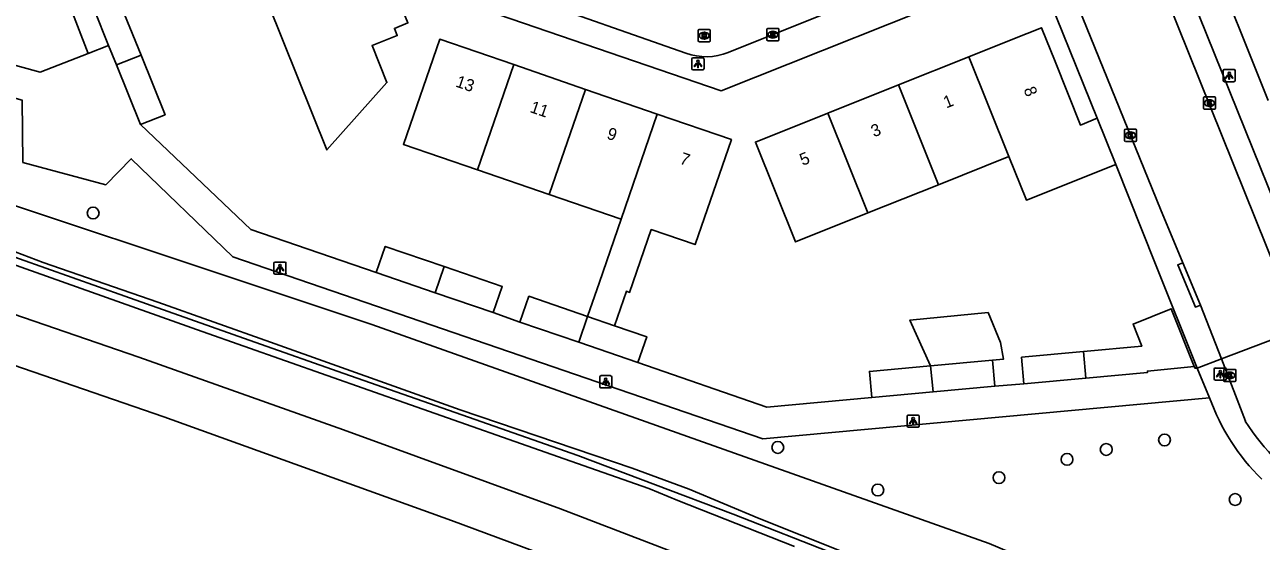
# Model space of a CAD drawing. Extents: x 162990 to 165007, y 383433 to 384336.
# Drawn here: x 163800.5 to 163902.7, y 383839.9 to 383882.7 of the extents above; entities that cross this region are included whole.
import ezdxf

# ---------------------------------------------------------------- set-up
doc = ezdxf.new("R2010")
doc.units = 0
for name, color, linetype in [('IMGEO_Boom', 7, 'Continuous'), ('IMGEO_Geluidsscherm', 7, 'Continuous'), ('IMGEO_Groenvoorziening', 7, 'Continuous'), ('IMGEO_Kolk', 7, 'Continuous'), ('IMGEO_Lichtpunt', 7, 'Continuous'), ('IMGEO_Muur', 7, 'Continuous'), ('IMGEO_Pand', 7, 'Continuous'), ('IMGEO_Pand_nummerreeks', 7, 'Continuous'), ('IMGEO_Rijbaan_lokaal_open', 7, 'Continuous'), ('IMGEO_Rioolput', 7, 'Continuous'), ('IMGEO_Spoor', 7, 'Continuous'), ('IMGEO_Spoorbaan_halfverhard', 7, 'Continuous'), ('IMGEO_Voetpad_open', 7, 'Continuous')]:
    doc.layers.add(name, color=color, linetype=linetype)

msp = doc.modelspace()

# ---------------------------------------------------------------- linework, layer by layer
at = {"layer": 'IMGEO_Boom'}
for centre in [(163806.18, 383867.07), (163894.75, 383848.3), (163862.78, 383847.68), (163889.93, 383847.51), (163886.69, 383846.69), (163881.06, 383845.18), (163871.05, 383844.15), (163900.59, 383843.37)]:
    msp.add_circle(centre, 0.489, dxfattribs=at)
at = {"layer": 'IMGEO_Geluidsscherm'}
msp.add_lwpolyline([(163774.05, 383875.4), (163781.73, 383872.71), (163782.12, 383872.57), (163783.25, 383869.74), (163787.97, 383868.23), (163797.39, 383864.74), (163802.04, 383862.98), (163811.54, 383859.69), (163820.83, 383856.4), (163836.52, 383850.79), (163850.74, 383845.96), (163855.44, 383844.22), (163861.23, 383841.81), (163878.61, 383834.88)], dxfattribs=at)
at = {"layer": 'IMGEO_Groenvoorziening'}
msp.add_lwpolyline([(163762.9, 383879.02), (163763.14, 383879.78), (163770.57, 383877.21), (163786.52, 383872.07), (163829.23, 383857.86), (163846.3, 383851.79), (163880.24, 383839.72), (163923.82, 383821.25), (163935.03, 383816.87), (163938.07, 383815.68), (164000, 383788.52), (164001.43, 383787.89), (164020.11, 383778.24), (164032.96, 383772.18), (164060.58, 383757.96), (164061.83, 383760.6)], dxfattribs=at)
at = {"layer": 'IMGEO_Kolk'}
for p, q in [((163861.87, 383881.41), (163861.87, 383882.26)), ((163861.95, 383882.33), (163862.8, 383882.33)), ((163862.87, 383882.26), (163862.87, 383881.41)), ((163862.8, 383881.33), (163861.95, 383881.33)), ((163862.36, 383882.11), (163862.39, 383882.11)), ((163862.38, 383881.55), (163862.36, 383881.55)), ((163897.97, 383875.75), (163897.97, 383876.6)), ((163898.04, 383876.68), (163898.89, 383876.68)), ((163898.45, 383876.45), (163898.48, 383876.45)), ((163898.97, 383876.6), (163898.97, 383875.75)), ((163898.89, 383875.67), (163898.04, 383875.67)), ((163898.48, 383875.9), (163898.45, 383875.9)), ((163891.43, 383873.08), (163891.43, 383873.93)), ((163891.51, 383874), (163892.36, 383874)), ((163891.92, 383873.78), (163891.95, 383873.78)), ((163891.94, 383873.22), (163891.92, 383873.22)), ((163892.44, 383873.93), (163892.44, 383873.08)), ((163892.36, 383873), (163891.51, 383873)), ((163899.65, 383853.21), (163899.65, 383854.06)), ((163899.72, 383854.14), (163900.57, 383854.14)), ((163900.13, 383853.92), (163900.16, 383853.92)), ((163900.65, 383854.06), (163900.65, 383853.21)), ((163900.57, 383853.14), (163899.72, 383853.14)), ((163900.16, 383853.36), (163900.13, 383853.36))]:
    msp.add_line(p, q, dxfattribs=at)
for points in [[(163861.87, 383881.41), (163861.87, 383882.26)], [(163861.95, 383882.33), (163862.8, 383882.33)], [(163862.87, 383882.26), (163862.87, 383881.41)], [(163862.8, 383881.33), (163861.95, 383881.33)], [(163862.19, 383882.03), (163862.32, 383882.03), (163862.32, 383881.88), (163862.45, 383882.03), (163862.61, 383882.03), (163862.46, 383881.88), (163862.62, 383881.63), (163862.46, 383881.63), (163862.38, 383881.8), (163862.32, 383881.73), (163862.32, 383881.63), (163862.19, 383881.63), (163862.19, 383882.03)], [(163897.97, 383875.75), (163897.97, 383876.6)], [(163898.04, 383876.68), (163898.89, 383876.68)], [(163898.29, 383876.37), (163898.41, 383876.37), (163898.41, 383876.22), (163898.54, 383876.37), (163898.7, 383876.37), (163898.56, 383876.22), (163898.71, 383875.97), (163898.56, 383875.97), (163898.47, 383876.14), (163898.41, 383876.07), (163898.41, 383875.97), (163898.29, 383875.97), (163898.29, 383876.37)], [(163898.97, 383876.6), (163898.97, 383875.75)], [(163898.89, 383875.67), (163898.04, 383875.67)], [(163891.43, 383873.08), (163891.43, 383873.93)], [(163891.51, 383874), (163892.36, 383874)], [(163891.75, 383873.7), (163891.88, 383873.7), (163891.88, 383873.55), (163892.01, 383873.7), (163892.17, 383873.7), (163892.03, 383873.55), (163892.18, 383873.3), (163892.03, 383873.3), (163891.94, 383873.47), (163891.88, 383873.4), (163891.88, 383873.3), (163891.75, 383873.3), (163891.75, 383873.7)], [(163892.44, 383873.93), (163892.44, 383873.08)], [(163892.36, 383873), (163891.51, 383873)], [(163899.65, 383853.21), (163899.65, 383854.06)], [(163899.72, 383854.14), (163900.57, 383854.14)], [(163899.97, 383853.84), (163900.09, 383853.84), (163900.09, 383853.69), (163900.22, 383853.84), (163900.38, 383853.84), (163900.24, 383853.69), (163900.39, 383853.44), (163900.24, 383853.44), (163900.15, 383853.6), (163900.09, 383853.54), (163900.09, 383853.44), (163899.97, 383853.44), (163899.97, 383853.84)], [(163900.65, 383854.06), (163900.65, 383853.21)], [(163900.57, 383853.14), (163899.72, 383853.14)]]:
    msp.add_lwpolyline(points, dxfattribs=at)
for centre, start, end in [((163861.95, 383882.26), 91.552, 178.448), ((163861.95, 383882.26), 91.552, 178.448), ((163862.8, 383882.26), 1.552, 88.448), ((163862.8, 383882.26), 1.552, 88.448), ((163861.95, 383881.41), 181.552, 268.448), ((163861.95, 383881.41), 181.552, 268.448), ((163862.8, 383881.41), 271.552, 358.448), ((163862.8, 383881.41), 271.552, 358.448), ((163898.04, 383876.6), 91.552, 178.448), ((163898.04, 383876.6), 91.552, 178.448), ((163898.89, 383876.6), 1.552, 88.448), ((163898.89, 383876.6), 1.552, 88.448), ((163898.04, 383875.75), 181.552, 268.448), ((163898.04, 383875.75), 181.552, 268.448), ((163898.89, 383875.75), 271.552, 358.448), ((163898.89, 383875.75), 271.552, 358.448), ((163891.51, 383873.93), 91.552, 178.448), ((163891.51, 383873.93), 91.552, 178.448), ((163891.51, 383873.08), 181.552, 268.448), ((163891.51, 383873.08), 181.552, 268.448), ((163892.36, 383873.93), 1.552, 88.448), ((163892.36, 383873.93), 1.552, 88.448), ((163892.36, 383873.08), 271.552, 358.448), ((163892.36, 383873.08), 271.552, 358.448), ((163899.72, 383854.06), 91.552, 178.448), ((163899.72, 383854.06), 91.552, 178.448), ((163900.57, 383854.06), 1.552, 88.448), ((163900.57, 383854.06), 1.552, 88.448), ((163899.72, 383853.21), 181.552, 268.448), ((163899.72, 383853.21), 181.552, 268.448), ((163900.57, 383853.21), 271.552, 358.448), ((163900.57, 383853.21), 271.552, 358.448)]:
    msp.add_arc(centre, 0.0765, start, end, dxfattribs=at)
for centre, major_axis, ratio, start_param, end_param in [((163862.36, 383881.83), (-0.387, 0.002), 0.722429, 4.712389, 7.853982), ((163862.38, 383881.83), (-0.39, 0.002), 0.717154, 1.570796, 4.712389), ((163898.45, 383876.17), (-0.387, 0.002), 0.722429, 4.712389, 7.853982), ((163898.48, 383876.17), (-0.39, 0.002), 0.717154, 1.570796, 4.712389), ((163891.92, 383873.5), (-0.387, 0.002), 0.722429, 4.712389, 7.853982), ((163891.95, 383873.5), (-0.39, 0.002), 0.717154, 1.570796, 4.712389), ((163900.13, 383853.64), (-0.387, 0.002), 0.722429, 4.712389, 7.853982), ((163900.16, 383853.64), (-0.39, 0.002), 0.717154, 1.570796, 4.712389)]:
    msp.add_ellipse(centre, major_axis=major_axis, ratio=ratio, start_param=start_param, end_param=end_param, dxfattribs=at)
at = {"layer": 'IMGEO_Lichtpunt'}
for p, q in [((163855.68, 383879.82), (163855.68, 383879.01)), ((163855.68, 383879.82), (163855.68, 383879.01)), ((163856.58, 383879.91), (163855.78, 383879.91)), ((163856.58, 383879.91), (163855.78, 383879.91)), ((163856.68, 383879.01), (163856.68, 383879.82)), ((163856.68, 383879.01), (163856.68, 383879.82)), ((163855.78, 383878.92), (163856.58, 383878.92)), ((163855.78, 383878.92), (163856.58, 383878.92)), ((163899.6, 383878.84), (163899.6, 383878.04)), ((163899.6, 383878.84), (163899.6, 383878.04)), ((163900.5, 383878.94), (163899.69, 383878.94)), ((163900.5, 383878.94), (163899.69, 383878.94)), ((163900.6, 383878.04), (163900.6, 383878.84)), ((163900.6, 383878.04), (163900.6, 383878.84)), ((163899.69, 383877.94), (163900.5, 383877.94)), ((163899.69, 383877.94), (163900.5, 383877.94)), ((163821.13, 383862.92), (163821.13, 383862.12)), ((163821.13, 383862.92), (163821.13, 383862.12)), ((163822.03, 383863.02), (163821.22, 383863.02)), ((163822.03, 383863.02), (163821.22, 383863.02)), ((163822.12, 383862.12), (163822.12, 383862.92)), ((163822.12, 383862.12), (163822.12, 383862.92)), ((163821.22, 383862.02), (163822.03, 383862.02)), ((163821.22, 383862.02), (163822.03, 383862.02)), ((163848.96, 383853.62), (163848.16, 383853.62)), ((163848.96, 383853.62), (163848.16, 383853.62)), ((163898.86, 383854.16), (163898.86, 383853.35)), ((163898.86, 383854.16), (163898.86, 383853.35)), ((163899.76, 383854.25), (163898.96, 383854.25)), ((163899.76, 383854.25), (163898.96, 383854.25)), ((163899.86, 383853.35), (163899.86, 383854.16)), ((163899.86, 383853.35), (163899.86, 383854.16)), ((163848.06, 383853.52), (163848.06, 383852.71)), ((163848.06, 383853.52), (163848.06, 383852.71)), ((163848.16, 383852.62), (163848.96, 383852.62)), ((163848.16, 383852.62), (163848.96, 383852.62)), ((163849.06, 383852.71), (163849.06, 383853.52)), ((163849.06, 383852.71), (163849.06, 383853.52)), ((163898.96, 383853.25), (163899.76, 383853.25)), ((163898.96, 383853.25), (163899.76, 383853.25)), ((163873.47, 383850.26), (163873.47, 383849.46)), ((163873.47, 383850.26), (163873.47, 383849.46)), ((163874.37, 383850.36), (163873.57, 383850.36)), ((163874.37, 383850.36), (163873.57, 383850.36)), ((163874.47, 383849.46), (163874.47, 383850.26)), ((163874.47, 383849.46), (163874.47, 383850.26)), ((163873.57, 383849.36), (163874.37, 383849.36)), ((163873.57, 383849.36), (163874.37, 383849.36))]:
    msp.add_line(p, q, dxfattribs=at)
for points in [[(163856.06, 383879.48), (163856.1, 383879.45), (163855.91, 383879.19), (163855.87, 383879.22), (163856.06, 383879.48)], [(163856.16, 383879.43), (163856.21, 383879.43), (163856.21, 383879.11), (163856.16, 383879.11), (163856.16, 383879.43)], [(163856.27, 383879.45), (163856.31, 383879.48), (163856.49, 383879.22), (163856.46, 383879.19), (163856.27, 383879.45)], [(163899.97, 383878.51), (163900.01, 383878.48), (163899.82, 383878.22), (163899.79, 383878.25), (163899.97, 383878.51)], [(163900.07, 383878.46), (163900.12, 383878.46), (163900.12, 383878.14), (163900.07, 383878.14), (163900.07, 383878.46)], [(163900.18, 383878.48), (163900.22, 383878.51), (163900.41, 383878.24), (163900.37, 383878.22), (163900.18, 383878.48)], [(163821.5, 383862.59), (163821.54, 383862.56), (163821.35, 383862.3), (163821.31, 383862.33), (163821.5, 383862.59)], [(163821.6, 383862.54), (163821.65, 383862.54), (163821.65, 383862.22), (163821.6, 383862.22), (163821.6, 383862.54)], [(163821.71, 383862.56), (163821.75, 383862.59), (163821.94, 383862.32), (163821.9, 383862.3), (163821.71, 383862.56)], [(163899.24, 383853.82), (163899.27, 383853.79), (163899.09, 383853.53), (163899.05, 383853.56), (163899.24, 383853.82)], [(163899.34, 383853.77), (163899.39, 383853.77), (163899.39, 383853.45), (163899.34, 383853.45), (163899.34, 383853.77)], [(163899.45, 383853.79), (163899.49, 383853.82), (163899.67, 383853.56), (163899.63, 383853.53), (163899.45, 383853.79)], [(163848.44, 383853.18), (163848.47, 383853.16), (163848.29, 383852.89), (163848.25, 383852.92), (163848.44, 383853.18)], [(163848.54, 383853.14), (163848.59, 383853.14), (163848.59, 383852.81), (163848.54, 383852.81), (163848.54, 383853.14)], [(163848.65, 383853.16), (163848.69, 383853.18), (163848.87, 383852.92), (163848.83, 383852.89), (163848.65, 383853.16)], [(163873.85, 383849.93), (163873.88, 383849.9), (163873.7, 383849.64), (163873.66, 383849.67), (163873.85, 383849.93)], [(163873.95, 383849.88), (163873.99, 383849.88), (163873.99, 383849.56), (163873.95, 383849.56), (163873.95, 383849.88)], [(163874.06, 383849.9), (163874.1, 383849.93), (163874.28, 383849.66), (163874.24, 383849.64), (163874.06, 383849.9)]]:
    msp.add_lwpolyline(points, dxfattribs=at)
for centre in [(163856.18, 383879.62), (163900.1, 383878.64), (163821.63, 383862.72), (163899.36, 383853.95), (163848.56, 383853.32), (163873.97, 383850.06)]:
    msp.add_circle(centre, 0.0994, dxfattribs=at)
for centre, start, end in [((163855.78, 383879.82), 90, 180), ((163855.78, 383879.82), 90, 180), ((163856.58, 383879.82), 0, 90), ((163856.58, 383879.82), 0, 90), ((163855.78, 383879.01), 180, 270), ((163855.78, 383879.01), 180, 270), ((163856.58, 383879.01), 270, 0), ((163856.58, 383879.01), 270, 360), ((163899.69, 383878.84), 90, 180), ((163899.69, 383878.84), 90, 180), ((163900.5, 383878.84), 0, 90), ((163900.5, 383878.84), 0, 90), ((163899.69, 383878.04), 180, 270), ((163899.69, 383878.04), 180, 270), ((163900.5, 383878.04), 270, 0), ((163900.5, 383878.04), 270, 360), ((163821.22, 383862.92), 90, 180), ((163821.22, 383862.92), 90, 180), ((163822.03, 383862.92), 0, 90), ((163822.03, 383862.92), 0, 90), ((163821.22, 383862.12), 180, 270), ((163821.22, 383862.12), 180, 270), ((163822.03, 383862.12), 270, 0), ((163822.03, 383862.12), 270, 360), ((163848.16, 383853.52), 90, 180), ((163848.16, 383853.52), 90, 180), ((163848.96, 383853.52), 0, 90), ((163848.96, 383853.52), 0, 90), ((163898.96, 383854.16), 90, 180), ((163898.96, 383854.16), 90, 180), ((163899.76, 383854.16), 0, 90), ((163899.76, 383854.16), 0, 90), ((163848.16, 383852.71), 180, 270), ((163848.16, 383852.71), 180, 270), ((163848.96, 383852.71), 270, 0), ((163848.96, 383852.71), 270, 360), ((163898.96, 383853.35), 180, 270), ((163898.96, 383853.35), 180, 270), ((163899.76, 383853.35), 270, 0), ((163899.76, 383853.35), 270, 360), ((163873.57, 383850.26), 90, 180), ((163873.57, 383850.26), 90, 180), ((163874.37, 383850.26), 0, 90), ((163874.37, 383850.26), 0, 90), ((163873.57, 383849.46), 180, 270), ((163873.57, 383849.46), 180, 270), ((163874.37, 383849.46), 270, 0), ((163874.37, 383849.46), 270, 360)]:
    msp.add_arc(centre, 0.0946, start, end, dxfattribs=at)
at = {"layer": 'IMGEO_Muur'}
for points in [[(163804.13, 383884.48), (163805.76, 383880.27)], [(163805.76, 383880.27), (163801.81, 383878.73), (163785.41, 383883.23), (163784.61, 383883.63)], [(163894.01, 383862.84), (163890.72, 383871.09)], [(163861.88, 383851), (163851.21, 383854.71)]]:
    msp.add_lwpolyline(points, dxfattribs=at)
at = {"layer": 'IMGEO_Pand'}
for points in [[(163820.64, 383884.38), (163825.51, 383872.3), (163830.47, 383877.86), (163829.24, 383880.92), (163831.32, 383881.76), (163831.08, 383882.35), (163832.2, 383882.8), (163831.18, 383885.31), (163830.07, 383884.86), (163828.92, 383887.71)], [(163806.26, 383883.92), (163808.29, 383884.74), (163810.14, 383880.14)], [(163806.26, 383883.92), (163807.46, 383880.94)], [(163878.58, 383880), (163882.2, 383881.45), (163884.58, 383882.4), (163885.7, 383879.6), (163887.8, 383874.35), (163889.19, 383874.91)], [(163837.95, 383870.65), (163831.83, 383872.75), (163834.83, 383881.45), (163840.95, 383879.35)], [(163808.11, 383879.33), (163807.46, 383880.94)], [(163810.14, 383880.14), (163808.11, 383879.33)], [(163808.11, 383879.33), (163810.1, 383874.39)], [(163810.1, 383874.39), (163812.13, 383875.21), (163810.14, 383880.14)], [(163840.95, 383879.35), (163837.95, 383870.65)], [(163846.89, 383877.3), (163840.95, 383879.35)], [(163872.75, 383877.67), (163878.58, 383880)], [(163881.89, 383871.74), (163878.58, 383880)], [(163843.89, 383868.6), (163846.89, 383877.3)], [(163846.89, 383877.3), (163852.82, 383875.26)], [(163866.92, 383875.34), (163872.75, 383877.67)], [(163872.75, 383877.67), (163876.06, 383869.41)], [(163849.28, 383857.75), (163850.26, 383860.6), (163850.53, 383860.5), (163852.32, 383865.7), (163855.94, 383864.46), (163858.94, 383873.15), (163852.82, 383875.26)], [(163852.82, 383875.26), (163849.83, 383866.56)], [(163870.23, 383867.08), (163864.24, 383864.68), (163860.93, 383872.94), (163866.92, 383875.34)], [(163870.23, 383867.08), (163866.92, 383875.34)], [(163889.19, 383874.91), (163890.72, 383871.09)], [(163881.89, 383871.74), (163876.06, 383869.41)], [(163890.72, 383871.09), (163883.33, 383868.14), (163881.89, 383871.74)], [(163837.95, 383870.65), (163843.89, 383868.6)], [(163876.06, 383869.41), (163870.23, 383867.08)], [(163849.83, 383866.56), (163843.89, 383868.6)], [(163849.83, 383866.56), (163848.04, 383861.36), (163847.06, 383858.52)], [(163835.2, 383862.64), (163830.33, 383864.31), (163829.59, 383862.15)], [(163829.59, 383862.15), (163834.46, 383860.48)], [(163834.46, 383860.48), (163835.2, 383862.64)], [(163839.26, 383858.84), (163840, 383860.99), (163835.2, 383862.64)], [(163834.46, 383860.48), (163839.26, 383858.84)], [(163847.06, 383858.52), (163842.2, 383860.19), (163841.46, 383858.05)], [(163880.53, 383854.9), (163881.45, 383854.99), (163881.18, 383856.37), (163880.16, 383858.84), (163873.7, 383858.22), (163875.4, 383854.43)], [(163888.05, 383855.61), (163892.86, 383856.05), (163892.15, 383857.89), (163895.3, 383859.15), (163897.21, 383854.37)], [(163841.46, 383858.05), (163846.33, 383856.38)], [(163846.33, 383856.38), (163847.06, 383858.52)], [(163847.06, 383858.52), (163849.28, 383857.75)], [(163851.21, 383854.71), (163851.94, 383856.84), (163849.28, 383857.75)], [(163846.33, 383856.38), (163851.21, 383854.71)], [(163880.53, 383854.9), (163875.4, 383854.43)], [(163880.73, 383852.75), (163880.53, 383854.9)], [(163883.13, 383852.95), (163882.93, 383855.14), (163888.05, 383855.61)], [(163888.05, 383855.61), (163888.25, 383853.42)], [(163875.4, 383854.43), (163870.35, 383853.97), (163870.55, 383851.82)], [(163875.61, 383852.28), (163875.4, 383854.43)], [(163888.25, 383853.42), (163893.35, 383853.89), (163893.34, 383853.99), (163897.21, 383854.37)], [(163875.61, 383852.28), (163880.73, 383852.75)], [(163883.13, 383852.95), (163888.25, 383853.42)], [(163870.55, 383851.82), (163875.61, 383852.28)]]:
    msp.add_lwpolyline(points, dxfattribs=at)
at = {"layer": 'IMGEO_Rijbaan_lokaal_open'}
for points in [[(163889.39, 383898.6), (163905.94, 383857.47)], [(163896.26, 383862.96), (163894.41, 383867.38), (163884.94, 383890.76)], [(163883.11, 383890.16), (163858.68, 383880.35)], [(163855.18, 383880.29), (163841.65, 383885.07), (163841.11, 383885.54)], [(163897.72, 383859.46), (163896.26, 383862.96)], [(163899.45, 383855), (163897.72, 383859.46)], [(163905.94, 383857.47), (163899.45, 383855)], [(163899.45, 383855), (163901.43, 383849.85)], [(163899.45, 383855), (163899.45, 383855)]]:
    msp.add_lwpolyline(points, dxfattribs=at)
for centre, radius, start, end in [((163856.85, 383884.93), 4.93, 250.224, 291.8682), ((163918.97, 383861.16), 20.87, 212.7923, 258.7749)]:
    msp.add_arc(centre, radius, start, end, dxfattribs=at)
at = {"layer": 'IMGEO_Rioolput'}
for p, q in [((163856.27, 383882.25), (163857.12, 383882.25)), ((163856.2, 383881.32), (163856.2, 383882.18)), ((163857.12, 383881.25), (163856.27, 383881.25)), ((163856.68, 383882.03), (163856.71, 383882.03)), ((163856.71, 383881.47), (163856.68, 383881.47)), ((163857.2, 383882.18), (163857.2, 383881.32))]:
    msp.add_line(p, q, dxfattribs=at)
for points in [[(163856.27, 383882.25), (163857.12, 383882.25)], [(163856.2, 383881.32), (163856.2, 383882.18)], [(163857.12, 383881.25), (163856.27, 383881.25)], [(163856.79, 383881.95), (163856.53, 383881.95), (163856.53, 383881.55)], [(163856.53, 383881.55), (163856.66, 383881.55), (163856.66, 383881.71), (163856.67, 383881.71)], [(163856.71, 383881.87), (163856.66, 383881.87), (163856.66, 383881.79)], [(163856.66, 383881.79), (163856.71, 383881.79)], [(163856.71, 383881.68), (163856.79, 383881.55), (163856.93, 383881.55), (163856.86, 383881.68)], [(163857.2, 383882.18), (163857.2, 383881.32)]]:
    msp.add_lwpolyline(points, dxfattribs=at)
for centre, radius, start, end in [((163856.27, 383882.18), 0.0765, 91.552, 178.448), ((163856.27, 383882.18), 0.0765, 91.552, 178.448), ((163857.12, 383882.18), 0.0765, 1.552, 88.448), ((163857.12, 383882.18), 0.0765, 1.552, 88.448), ((163856.27, 383881.33), 0.0765, 181.552, 268.448), ((163856.27, 383881.33), 0.0765, 181.552, 268.448), ((163856.67, 383881.66), 0.0533, 26.0293, 88.6989), ((163856.72, 383881.77), 0.0964, 77.0061, 93.1865), ((163856.69, 383881.98), 0.19, 274.7715, 282.9687), ((163856.73, 383881.83), 0.0378, 276.6634, 79.6772), ((163856.78, 383881.84), 0.109, 350.3612, 89.416), ((163856.78, 383881.84), 0.112, 277.5842, 350.9817), ((163856.77, 383881.62), 0.108, 29.5134, 73.7905), ((163857.12, 383881.33), 0.0765, 271.552, 358.448), ((163857.12, 383881.33), 0.0765, 271.552, 358.448)]:
    msp.add_arc(centre, radius, start, end, dxfattribs=at)
for centre, major_axis, ratio, start_param, end_param in [((163856.68, 383881.75), (-0.387, 0.002), 0.722429, 4.712389, 7.853982), ((163856.71, 383881.75), (-0.39, 0.002), 0.717154, 1.570796, 4.712389)]:
    msp.add_ellipse(centre, major_axis=major_axis, ratio=ratio, start_param=start_param, end_param=end_param, dxfattribs=at)
at = {"layer": 'IMGEO_Spoor'}
for points in [[(163711.1, 383886.58), (163738.85, 383878.42), (163767.19, 383869.54), (163783.09, 383864.4), (163809.96, 383855.14), (163826.89, 383849.13), (163844.81, 383842.61), (163875.4, 383830.86)], [(163718.44, 383880.35), (163738.83, 383874.36), (163758.35, 383868.28), (163784.55, 383859.66), (163812.02, 383850.2), (163835.8, 383841.64), (163859.38, 383832.87)]]:
    msp.add_lwpolyline(points, dxfattribs=at)
at = {"layer": 'IMGEO_Spoorbaan_halfverhard'}
for points in [[(163878.61, 383834.88), (163861.23, 383841.81), (163855.44, 383844.22), (163850.74, 383845.96), (163836.52, 383850.79), (163820.83, 383856.4), (163811.54, 383859.69), (163802.04, 383862.98), (163797.39, 383864.74), (163787.97, 383868.23), (163783.25, 383869.74), (163782.21, 383872.34)], [(163852.12, 383844.29), (163845.11, 383846.73), (163832.42, 383851.2), (163815.2, 383857.27), (163796.88, 383863.78), (163787.05, 383867.31), (163782.76, 383868.75), (163783.26, 383869.24), (163786.48, 383868.16), (163792.56, 383865.98), (163800.09, 383863.28), (163808.79, 383860.2), (163819.56, 383856.38), (163826.91, 383853.8), (163837.2, 383850.18), (163846.24, 383847), (163859.1, 383842.17), (163867.65, 383838.8)], [(163864.15, 383839.49), (163854.52, 383843.29), (163852.12, 383844.29)]]:
    msp.add_lwpolyline(points, dxfattribs=at)
at = {"layer": 'IMGEO_Voetpad_open'}
for points in [[(163884.09, 383887.57), (163883.49, 383887.33), (163880.39, 383886.09), (163858.11, 383877.17), (163833.54, 383885.63), (163827.44, 383900.76)], [(163906.44, 383861.52), (163892.61, 383895.86)], [(163898.23, 383889.14), (163903.32, 383876.39)], [(163884.09, 383887.57), (163889.19, 383874.91)], [(163898.48, 383851.79), (163861.54, 383848.4), (163817.73, 383863.45), (163809.33, 383871.57), (163807.22, 383869.41), (163800.38, 383871.26), (163800.3, 383876.42), (163784.84, 383880.72), (163775.65, 383884.91)], [(163805.76, 383880.27), (163804.13, 383884.48)], [(163784.61, 383883.63), (163785.41, 383883.23), (163801.81, 383878.73), (163805.76, 383880.27)], [(163807.46, 383880.94), (163805.76, 383880.27)], [(163810.1, 383874.39), (163819.21, 383865.71), (163829.59, 383862.15)], [(163890.72, 383871.09), (163894.01, 383862.84), (163897.46, 383854.25)], [(163897.72, 383859.46), (163897.3, 383859.29), (163895.84, 383862.79), (163896.26, 383862.96)], [(163839.26, 383858.84), (163841.46, 383858.05)], [(163851.21, 383854.71), (163861.88, 383851), (163870.55, 383851.82)], [(163899.45, 383855), (163897.46, 383854.25)], [(163897.21, 383854.37), (163897.27, 383854.23), (163897.46, 383854.25)], [(163897.46, 383854.25), (163898.48, 383851.79)], [(163880.73, 383852.75), (163883.13, 383852.95)]]:
    msp.add_lwpolyline(points, dxfattribs=at)
msp.add_arc((163915.33, 383857.84), 17.91, 199.7657, 225.5332, dxfattribs=at)

# ---------------------------------------------------------------- texts
at = {"layer": 'IMGEO_Pand_nummerreeks'}
for s, rotation, p in [('13', 341.0051, (163836.08, 383877.55)), ('8', 291.805, (163883.08, 383877.3)), ('11', 341.0051, (163842.22, 383875.44)), ('1', 21.8039, (163876.71, 383875.72)), ('9', 341.0051, (163848.57, 383873.25)), ('3', 21.8039, (163870.72, 383873.33)), ('7', 341.0064, (163854.6, 383871.18)), ('5', 21.8039, (163864.83, 383870.97))]:
    msp.add_text(s, height=1, rotation=rotation, dxfattribs=at).set_placement(p)

doc.saveas('drawing.dxf')
